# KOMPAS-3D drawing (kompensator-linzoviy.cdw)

Views: Вид 1, Вид 2
Referenced files: Компенсатор СБ.cdw
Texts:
  Компенсатор линзовый Сборочный чертёж
  Инженер-конструктор
  Химстроймонтаж
  ГОСТ14771-76-С2
  ГОСТ14771-76-Т1  2
  *Размер для справок
  Сварку произвести проволокой ОК Аutrod 16.32  в  среде
  углекислого газа ГОСТ8050-85
  Контроль качества сварных швов  по  РД-26-11 -85 "
  Инструкция по контролю сварных соединений не доступных для
  проведения радиографического и ультразвукового контроля"
  -визуально-послойный контроль,внешний осмотр и измерения.
  Компенсатор линзовый
  Сборочный чертёж
Dimensions and other numbers on the sheet: 762; 54; 108; 21; 600; 1; 2; 3; 1:4; 21,63; 0; 4; 5; 6; 7; 8; 9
